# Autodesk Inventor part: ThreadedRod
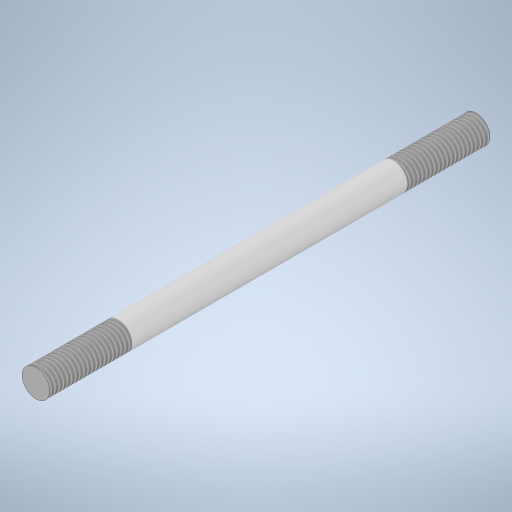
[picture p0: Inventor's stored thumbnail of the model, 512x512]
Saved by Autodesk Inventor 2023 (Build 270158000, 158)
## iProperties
Created: 2023-11
Part Number: ThreadedRod
Material: Generic
Document SubType Name: Modeling
Designer: tornqvih
Density: 1 g/cm^3
Appearance: Default
Author: tornqvih
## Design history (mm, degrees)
sketch "Sketch1"
  geometry: C1 r 5 at (0, 0); 1 further point
  constraints: 1 centre point, 1 coincident
  dimensions: "d0" = 10 diameter of C1
extrude "Extrusion1" new body sketch "Sketch1" distance "d1" = 160; taper "d2" = 0 deg
thread "Thread1" dims "d3" = 30, "d4" = 0
thread "Thread2" dims "d5" = 30, "d6" = 0
body "Solid1"
